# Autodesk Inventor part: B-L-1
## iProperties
Created: 2005-12
Part Number: B-L-1
Cost Center: 1,221 kg
Document SubType Name: Modeling
Designer: KK
Authority: 1221500 mm^3
Description: Edelstahll-Gußgehäuse
AIMD_DESCRIPTION: Bodeneinbauleuchte
SaveDate: 2005-12-19
SaveTime: 15:38
TotalMass: 1,221 kg
TotalVolume: 1221500 mm^3
Author: KK
Title: Edelstahll-Gußgehäuse
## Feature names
1. Erhebung1
2. Extrusion1
3. Extrusion2
4. Extrusion3
5. Fase1 [Chamfer]
6. Extrusion4
7. Fase2 [Chamfer]
8. Extrusion5
9. Spiegeln1 [Mirror]
10. Extrusion7
11. Extrusion8
12. Extrusion9
13. Spiegeln2 [Mirror]
14. Extrusion10
15. Spiegeln3 [Mirror]
